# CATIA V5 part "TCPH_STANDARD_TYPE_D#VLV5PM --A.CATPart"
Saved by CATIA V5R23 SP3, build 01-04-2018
Part number: TCPH_STANDARD_TYPE_D#VLV5N5
Revision: --A
Nomenclature: _
Description: TCPH_STANDARD_TYPE_D
Property "MAT": "PR"
Property "Long Description": "CRYOP_HOUSING_UPPER_POSITION_C+GS"
Property "PBS Short": "3.1"
Property "VAC & FUEL CLASS": "N"
Property "GAS CLASS": "N"
Property "WATER CLASS": "N"
Property "ELEC CLASS": "N"
Property "CODAC CLASS": "N"
Property "RH CLASS": "N"
Property "HEAT CLASS": "N"
Property "DIAG CLASS": "N"
Property "CRYO CLASS": "N"
Property "NEU CLASS": "N"
Property "ASSY CLASS": "N"
Property "SAFETY CLASS": "N"
Property "QA CLASS": "N"
Property "DEPT": "_"
Property "DIVN": "_"
Property "GROUP": "_"
Property "UNIT": "_"
Property "PARTY": "_"
Property "RO": "BHARDWA"
Property "RE": "VITUPIG"
Property "PRO": "---"
Property "Part Code": "TXT1"
Property "Part Origin": "ITER-P-3282KS+AA+-0"
Property "ITER Part Version": "-1"
Property "PBS Full Meaning": "VACUUM PUMPING"
Property "Date": "2005-11-11-09.18.13.000000"
Property "Responsible": "GLISSC"
Property "Site Resp": "SITE_AA"
Property "Organization": "ITER"
Property "Former PN": "ITER-P-3282KS"
Property "CHK MAT": "UNSYNC"
Property "PBS": "3.1 VACUUM PUMPING"
Property "Sig. Point Calc.": "N"
Property "ShortDescMig": "CRYOP_HOUSING_UPPER"
Property "PbsLevel1Mig": "31"
Property "PNMig": "235NFX"
Property "User In Enovia": "VAUQUEJ"
Property "Life Cycle Status": "Approved"
Property "ID": "VLV5N5"
Property "AT": "PD"
Property "PBS 1": "24"
Property "PBS 2": "CR"
Property "PBS 3": "LC"
Property "LONG": "_"
Property "PREF": "Y"
Property "Change Type": "Minor"
Property "Maturity Level": "CD"
Property "Export Number": "_"
Property "REP": "CM"
Property "Object Type": "_"
Property "CADENAS_ID": "_"
Property "Description Modification": "DR-34 and DR-35"
Property "Description Documents": "_"
Property "BOM": "_"
Property "External Part ID": "ITER-C-235NEF"
Publications: "SHELL", "INTERFACE_PLATE", "VERTICAL_PLATES", "FLANGE", "INNER_CYLINDER", "POCKET", "TUBE_B1_TO_B5", "RH_POCKET", "VACUUM_PIPE"
Material "Stainless steel": density 8030 kg/m3, Young's modulus 2e+11 Pa, Poisson ratio 0.266, thermal expansion 1.17e-05 1/K
Bounding box of the stored display mesh (mm): x 13380 to 16870, y -1350 to 1350, z -6313 to -2983
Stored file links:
  C:\Users\pandeym\Desktop\__TCPH\TCPH_STANDARD_TYPE_D#VLV5PM --A.CATPart
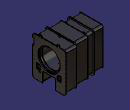
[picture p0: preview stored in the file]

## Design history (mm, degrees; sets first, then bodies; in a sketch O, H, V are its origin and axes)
Set1
  Line1 "CRYOPUMP_CENTER_AXIS": linked copy from another document
  DatumSurface1 "SURFACE_IN": linked copy from another document
  DatumSurface2 "SURFACE_OUT": linked copy from another document
  Sketch1 "TCPH_INNER_CYLINDER", origin (0, 0, 0), H (-1, 0, 0), V (0, 0, 1), geometry linked from another document
  Sketch2 "TCPH_VACUUM_PUMP_INTERFACE", origin (0, 0, 0), H (-1, 0, 0), V (0, 0, 1), geometry linked from another document
  Plane1 "CRYOPUMP_INTERFACE_PLANE_02": linked copy from another document
  Plane2 "CRYOPUMP_INTERFACE_PLANE_03": linked copy from another document
  Plane3 "CRYOPUMP_INTERFACE_PLANE_04": linked copy from another document
  Sketch3 "RH_RAIL_POCKETS", origin (15875, 0, 0), H (0, 1, 0), V (0, 0, 1), geometry linked from another document
  Sketch4 "CRYOPUMP_HOLES", origin (16720, 0, 0), H (0, 1, 0), V (0, 0, 1), geometry linked from another document
  Plane4 "CRYOPUMP_INTERFACE_PLANE_09": linked copy from another document
  Plane5 "CRYOPUMP_INTERFACE_PLANE_10": linked copy from another document
  Plane6 "CRYOPUMP_INTERFACE_PLANE_08": linked copy from another document
  Plane7 "CRYOPUMP_INTERFACE_PLANE_07": linked copy from another document
  Sketch5 "INNER_PLATES_HOLES", origin (15875, 0, 0), H (0, 1, 0), V (0, 0, 1), geometry linked from another document
  Sketch6 "TCPH_STANDARD_SHELL_03", origin (14800, 0, 0), H (0, 1, 0), V (0, 0, 1), geometry linked from another document
  Sketch7 "TCPH_FLANGE", origin (14800, 0, 0), H (0, 1, 0), V (0, 0, 1), geometry linked from another document
  Sketch8 "TCPH_STANDARD_SHELL_04", origin (13400, 0, 0), H (0, 1, 0), V (0, 0, 1), geometry linked from another document
  Sketch9 "TCPH_STANDARD_SHELL_02", origin (15855, 0, 0), H (0, 1, 0), V (0, 0, 1), geometry linked from another document
  Sketch10 "OUTER_VERTICAL_PLATES", origin (13380, 0, 0), H (0, 1, 0), V (0, 0, 1), geometry linked from another document
  Sketch11 "TCPH_TYPE_A_SHELL_01", origin (16750, 0, 0), H (0, 1, 0), V (0, 0, 1), geometry linked from another document
  Sketch12 "INTERFACE_PLATE", origin (16800, 0, 0), H (0, 1, 0), V (0, 0, 1), geometry linked from another document
  Sketch13 "SOCKET_PROFIL", origin (15540, 0, 0), H (0, 1, 0), V (0, 0, 1), geometry linked from another document
  Sketch14 "VERTICAL_PLATE_01", origin (15855, 0, 0), H (0, 1, 0), V (0, 0, 1), geometry linked from another document
  Sketch15 "VERTICAL_PLATE_02", origin (14820, 0, 0), H (0, 1, 0), V (0, 0, 1), geometry linked from another document
  DatumCurve1 "MONITORING_PIPE_PROFIL": linked copy from another document
  Sketch16 "LIFTING_PADS_HOLES", origin (0, 0, -3193), H (1, 0, 0), V (0, 1, 0), geometry linked from another document
  Sketch17 "TEMPORARY_FLANGE_HOLES", origin (16800, 0, 0), H (0, 1, 0), V (0, 0, 1), geometry linked from another document
  Sketch18 "VACUUM_PIPE_SECTION_1", origin (0, 0, -6293), H (1, 0, 0), V (0, 1, 0), geometry linked from another document
  Sketch19 "RH_RAILS_HOLES", origin (16830, 0, 0), H (0, 1, 0), V (0, 0, 1), geometry linked from another document
  Sketch20 "RH_PINS", origin (15875, 0, 0), H (0, 1, 0), V (0, 0, 1), geometry linked from another document
  Sketch21 "RH_RAILS_INTERFACE", origin (16830, 0, 0), H (0, 1, 0), V (0, 0, 1), geometry linked from another document
  Sketch22 "DIAG_TCPH_HOLES", origin (13380, 0, 0), H (0, 1, 0), V (0, 0, 1), geometry linked from another document
  Sketch23 "DIAG_TCPH_PIPES", origin (13380, 0, 0), H (0, 1, 0), V (0, 0, 1), geometry linked from another document
  Sketch24 "FLANGE_DOCKING_PINS", origin (16800, 0, 0), H (0, 1, 0), V (0, 0, 1), geometry linked from another document
  Sketch25 "VERTICAL_PLATE_04", origin (15855, 0, 0), H (0, 1, 0), V (0, 0, 1), geometry linked from another document
  Sketch26 "TCPH_SHELL_06", origin (15855, 0, 0), H (0, 1, 0), V (0, 0, 1), geometry linked from another document
  Sketch27 "TCPH_SHELL_05", origin (16750, 0, 0), H (0, 1, 0), V (0, 0, 1), geometry linked from another document
  Sketch28 "VERTICAL_PLATE_05", origin (14820, 0, 0), H (0, 1, 0), V (0, 0, 1), geometry linked from another document
  Sketch29 "INTERFACE_PLATE_P12", origin (16800, 0, 0), H (0, 1, 0), V (0, 0, 1), geometry linked from another document
Set2 "CONST"
  Extract1: ExtractElem face of Pad14
  Extract2: ExtractElem end face of Pad14
  Extract3: ExtractElem face of Pad14
  Extract4: ExtractElem face of Pad14
  Join1: Elements (Extract4; Extract3; Extract2; Extract1)
Body1 "SHELL" (main body)
  Pad1: profile Sketch26, direction (1, 0, 0), up to start face of Pad9, opposite side up to Plane3
  Pad2: profile Sketch6, direction (1, 0, 0), up to face of Solid1, opposite side up to Plane6
  Pad3: profile Sketch27, direction (1, 0, 0), up to Plane2
  Body2 "FLANGE"
    Solid1: linked copy from another document
  Remove1: tool Body2
  Split1: SplitPlane Join1
  Pad4: profile Sketch8, direction (1, 0, 0), up to DatumSurface1
  Sketch30 on face of Pad1, origin (0, 0, -6213), H (1, 0, 0), V (0, -1, 0)
    projected circle E1 centre (15565, 780) radius 77.04 from edge of Sketch18
  Pocket1: profile Sketch30, direction (0, 0, 1), up to face of Pad1
Body3 "INTERFACE_PLATE"
  Pad5: profile Sketch29, direction (1, 0, 0), up to Plane1
  Shaft1: profile Sketch2, axis axis of face of Shaft2, angle 360
  Pad6: profile Sketch24, direction (1, 0, 0), length 70
  Chamfer1: length 20, angle 30, on edge [face of Pad6 | end face of Pad6]; end face of Pad6
  Sketch31 on face of Shaft1, origin (16800, -579.3117, -3160), H (0, 1, 0), V (0, 0, 1)
    point P1 (579.3117, -3)
    reference projected point E1 (579.3117, -3) from vertex of Sketch17
    coincidence: P1 E1
  Hole1: placed by Sketch31, at (16800, 0, -3163) direction (-1, 0, 0), diameter 22, through (limit type 3)
  UserPattern1: of Hole1, copies 49, at the points of Sketch17
  Sketch32 on face of Shaft1, origin (16720, -88.6401, -3549.6454), H (0, 1, 0), V (0, 0, 1)
    point P1 (-759.3599, -843.3546)
    reference projected point E1 (-759.3599, -843.3546) from vertex of Sketch4
    coincidence: E1 P1
  Hole2: placed by Sketch32, at (16720, -848, -4393) direction (-1, 0, 0), diameter 20.752, depth 80, V-bottom angle 120, threaded "M24", thread diameter 24, thread depth 70, pitch 3
  UserPattern2: of Hole2, copies 61, at the points of Sketch4
  Pocket2: profile Sketch22, direction (-1, 0, 0), up to face of Shaft1
  Pad7: profile Sketch21, direction (1, 0, 0), up to face of Shaft1
  Sketch33 on start face of Pad7, origin (16830, -750, -5093), H (0, 1, 0), V (0, 0, 1)
    point P1 (-50, 0)
    reference projected point E1 (-50, 0) from vertex of Sketch19
    coincidence: E1 P1
  Hole3: placed by Sketch33, at (16830, -800, -5093) direction (-1, 0, 0), diameter 13.835, up to face of Shaft1, threaded "M16", thread diameter 16, thread depth 30, pitch 2
  UserPattern3: of Hole3, copies 14, at the points of Sketch19
Body4 "VERTICAL_PLATES"
  Pad8: profile Sketch25, direction (1, 0, 0), up to Plane3, opposite side up to Plane2
  Pad9: profile Sketch28, direction (1, 0, 0), up to Plane6, opposite side up to Plane7
  Pad10: profile Sketch10, direction (1, 0, 0), up to Plane5, opposite side up to Plane4
  Pocket3: profile Sketch5, direction (-1, 0, 0), up to start face of Pad10
  Split2: SplitPlane Join1
  Pocket4: profile Sketch22, direction (-1, 0, 0), through (limit type 3)
  Sketch34 on start face of Pad16, origin (15825, 0, 0), H (0, 1, 0), V (0, 0, 1)
    projected line E1 (-736.7157, -5093) -> (-970, -5093) from edge of Sketch3
    projected line E2 (-970, -5468) -> (-645, -5468) from edge of Sketch3
    projected line E3 (-645, -5468) -> (-645, -5184.7157) from edge of Sketch3
    projected line E4 (-645, -5184.7157) -> (-736.7157, -5093) from edge of Sketch3
    projected line E5 (-970, -5093) -> (-970, -5468) from edge of Sketch3
    projected line E6 (645, -5184.7157) -> (645, -5468) from edge of Sketch3
    projected line E7 (736.7157, -5093) -> (645, -5184.7157) from edge of Sketch3
    projected line E8 (970, -5093) -> (736.7157, -5093) from edge of Sketch3
    projected line E9 (970, -5468) -> (970, -5093) from edge of Sketch3
    projected line E10 (645, -5468) -> (970, -5468) from edge of Sketch3
  Pocket5: profile Sketch34, direction (-1, 0, 0), up to start face of Pad8
  Thickness1: Face (face of Pocket4; face of Pocket4; face of Pocket4), Thickness -15.45
  Thickness2: Face (face of Pocket4; face of Pocket4), Thickness -12.85
Body5 "FLANGE"
  Pad11: profile Sketch7, direction (1, 0, 0), up to DatumSurface1, opposite side up to DatumSurface2
  Pocket6: profile Sketch5, direction (-1, 0, 0), through (limit type 6)
  Sketch35 "DIAG_TCPH_HOLES", origin (13380, 0, 0), H (0, 1, 0), V (0, 0, 1), geometry linked from another document
  Pocket7: profile Sketch35, direction (-1, 0, 0), through (limit type 3)
  Sketch36 on end face of Pad10, origin (13380, 0, 0), H (0, -1, 0), V (0, 0, 1)
    circle A1 centre (-990, -3363) radius 2
    point P1 (-990, -3363)
    construction line L1 (-990, -3363.1789) -> (-990, -3371.8598)
    point P4 (-990, -3363.1789)
    point P5 (-990, -3371.8598)
    axis line L2 (-1063.4425, -3363) -> (-1052.2485, -3363)
    point P6 (-1063.4425, -3363)
    point P7 (-1052.2485, -3363)
    reference projected point E2 (-990, -3363) from vertex of DatumCurve1
    reference projected point E3 (-990, -3363) from vertex of DatumCurve1
    reference intersected line E4 through (0, 0) direction (0, -1) from zx-plane
    point P11 (990, -3371.8598)
    point P12 (990, -3363.1789)
    construction line L3 (990, -3363.1789) -> (990, -3371.8598)
    point P13 (1052.2485, -3363)
    point P14 (1063.4425, -3363)
    construction line L4 (1063.4425, -3363) -> (1052.2485, -3363)
    circle A2 centre (990, -3363) radius 2
    radius A1 = 2
    distance P1 L2 = 0
    vertical: L1 V
    horizontal: L2 H
    coincidence: L2 E2, L1 E3, P1 L1
    symmetry: P5 P11 E4, P4 P12 E4, L1 L3 E4, P7 P13 E4, P6 P14 E4, L2 L4 E4, A1 A2 E4
  Pocket8: profile Sketch36, direction (1, 0, 0), through (limit type 3)
  Sketch37 on end face of Pad10, origin (13380, 0, 0), H (0, -1, 0), V (0, 0, 1)
    projected circle E1 centre (-990, -3363) radius 2 from edge [face of Pocket8 from Sketch36.A1 | end face of Pad11]
    circle A1 centre (-990, -3363) radius 3
    point P1 (-990, -3363)
    reference intersected line E4 through (0, 0) direction (0, -1) from zx-plane
    circle A2 centre (990, -3363) radius 3
    circle A3 centre (990, -3363) radius 2
    distance A1 E1 = 1
    concentricity: P1 E1
    symmetry: E1 A3 E4, A1 A2 E4
  Pad12: profile Sketch37, direction (1, 0, 0), length 885, opposite side length -765
  Thickness3: Face (face of Pocket7; face of Pocket7; face of Pocket7), Thickness -15.45
  Thickness4: Face face of Pocket7, Thickness -12.85
Body6 "INNER_CYLINDER"
  Shaft2: profile Sketch1, axis Line1, angle 360
Body7 "POCKET"
  Pad13: profile Sketch13, direction (1, 0, 0), up to end face of Pad5
  Sketch38 on start face of Pad13, origin (15540, 0, 0), H (0, -1, 0), V (0, 0, 1)
    projected line E1 (615, -5343) -> (615, -6253) from edge [start face of Pad13 | face of Pad13]
    projected line E2 (-615, -6253) -> (-615, -5343) from edge [start face of Pad13 | face of Pad13]
    projected line E3 (-615, -5343) -> (615, -5343) from edge [start face of Pad13 | face of Pad13]
    line L1 (-615, -6253) -> (615, -6253)
    horizontal: L1 H
  Pad14: profile Sketch38, direction (-1, 0, 0), length 20
  Pocket9: profile Sketch22, direction (-1, 0, 0), up to start face of Pad14
Body8 "TUBE_B1_TO_B5"
  Pad15: profile Sketch23, direction (-1, 0, 0), up to face of Shaft1
  Sketch39 on face of Shaft1, origin (16800, 0, 0), H (0, -1, 0), V (0, 0, 1)
    line L1 (-549.7423, -5417.269) -> (541.682, -5417.269)
    line L2 (541.682, -5417.269) -> (541.682, -5843.7993)
    line L3 (541.682, -5843.7993) -> (-549.7423, -5843.7993)
    line L4 (-549.7423, -5843.7993) -> (-549.7423, -5417.269)
    horizontal: L1 H, L3 H
    vertical: L2 V, L4 V
  Pocket10: profile Sketch39, direction (1, 0, 0), up to start face of Pad13, offset -245
Body9 "RH_POCKET"
  Pad16: profile Sketch3, direction (1, 0, 0), up to end face of Pad5, opposite side length 50
  Pad17: profile Sketch34, direction (-1, 0, 0), length 20
  Body10 "POCKET"
    Solid2: linked copy from another document
  Remove2: tool Body10
  Pad18: profile Sketch20, direction (1, 0, 0), up to start face of Pad17
  Chamfer2: length 20, angle 30, on edge [face of Pad18 | start face of Pad18] (x2)
Body11 "VACUUM_PIPE"
  Pad19: profile Sketch18, direction (0, 0, 1), length 80
Body12 "LIFTING_PADS"
  Sketch40 "LIFTING_PADS", origin (0, 0, -3193), H (1, 0, 0), V (0, 1, 0), geometry linked from another document
  Pad20: profile Sketch40, direction (0, 0, 1), length 60
  Sketch41 on end face of Pad20, origin (15830, 0, -3133), H (1, 0, 0), V (0, 1, 0)
    point P1 (100, 0)
    reference projected point E1 (100, 0) from vertex of Sketch16
    coincidence: P1 E1
  Hole4: placed by Sketch41, at (15930, 0, -3133) direction (0, 0, -1), diameter 31.67, through (limit type 3), threaded "M36", thread diameter 36, thread depth 60, pitch 4
  UserPattern4: of Hole4, copies 3, at the points of Sketch16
